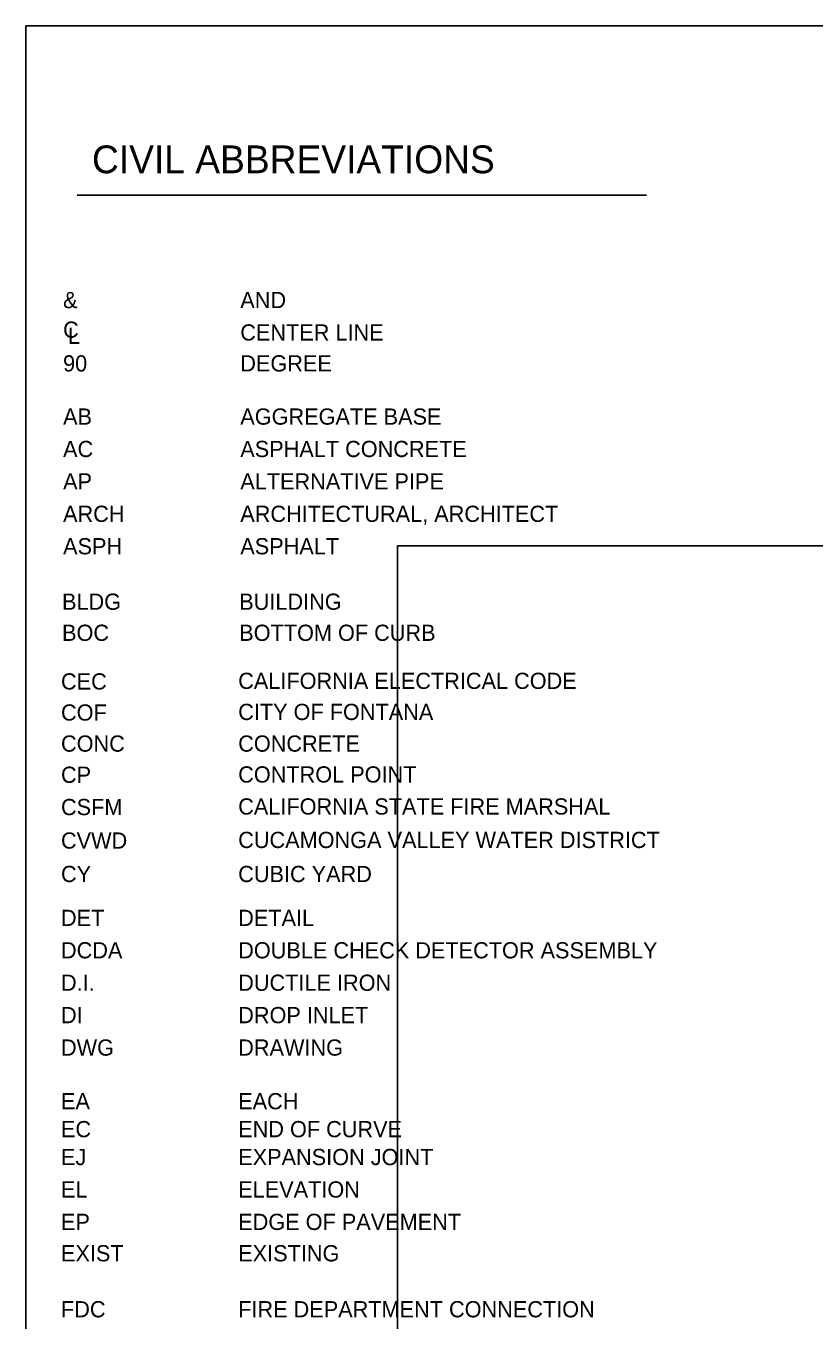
# Model space of a CAD drawing. Extents: x 6711682 to 6713077, y 1869209 to 1870525.
# Drawn here: x 6711682 to 6712022, y 1869939 to 1870497 of the extents above; entities that cross this region are included whole.
import ezdxf

# ---------------------------------------------------------------- set-up
doc = ezdxf.new("R2010")
doc.units = 0
for name, color, linetype in [('G-TTLB-VIEW', 7, 'Continuous'), ('Nongeo Data(60)', 7, 'Continuous'), ('Sheet Format(10)', 7, 'Continuous')]:
    doc.layers.add(name, color=color, linetype=linetype)

msp = doc.modelspace()

# ---------------------------------------------------------------- linework, layer by layer
at = {"layer": 'G-TTLB-VIEW'}
for points in [[(6711681.56, 1870497.47), (6713076.58, 1870497.47), (6713076.58, 1869377.45), (6711681.56, 1869377.45)], [(6711841.98, 1870272.86), (6712888.25, 1870272.86), (6712888.25, 1869432.85), (6711841.98, 1869432.85)]]:
    msp.add_lwpolyline(points, close=True, dxfattribs=at)
at = {"layer": 'Nongeo Data(60)'}
msp.add_line((6711703.77, 1870424.32), (6711949.47, 1870424.32), dxfattribs=at)

# ---------------------------------------------------------------- texts
msp.add_text('CIVIL ABBREVIATIONS', height=12, rotation=0, dxfattribs=at).set_placement((6711710.11, 1870433.83))
at = {"layer": 'Sheet Format(10)'}
for s, p in [('&', (6711697.62, 1870375.58)), ('AND', (6711774.13, 1870375.58)), ('C', (6711697.62, 1870362.79)), ('CENTER LINE', (6711774.13, 1870361.58)), ('L', (6711699.69, 1870360.11)), ('90', (6711697.62, 1870348.23)), ('DEGREE', (6711774.13, 1870348.23)), ('AB', (6711697.62, 1870325.26)), ('AGGREGATE BASE', (6711774.13, 1870325.26)), ('AC', (6711697.62, 1870311.26)), ('ASPHALT CONCRETE', (6711774.13, 1870311.26)), ('AP', (6711697.62, 1870297.26)), ('ALTERNATIVE PIPE', (6711774.13, 1870297.26)), ('ARCH', (6711697.62, 1870283.26)), ('ARCHITECTURAL, ARCHITECT', (6711774.13, 1870283.26)), ('ASPH', (6711697.62, 1870269.26)), ('ASPHALT', (6711774.13, 1870269.26)), ('BLDG', (6711697.17, 1870245.31)), ('BUILDING', (6711773.68, 1870245.31)), ('BOC', (6711697.17, 1870231.89)), ('BOTTOM OF CURB', (6711773.68, 1870231.89)), ('CEC', (6711696.72, 1870210.88)), ('CALIFORNIA ELECTRICAL CODE', (6711773.23, 1870211.13)), ('COF', (6711696.72, 1870197.46)), ('CITY OF FONTANA', (6711773.23, 1870197.71)), ('CONC', (6711696.72, 1870184.04)), ('CONCRETE', (6711773.23, 1870184.04)), ('CP', (6711696.72, 1870170.58)), ('CONTROL POINT', (6711773.23, 1870170.71)), ('CSFM', (6711696.72, 1870156.63)), ('CALIFORNIA STATE FIRE MARSHAL', (6711773.23, 1870156.88)), ('CUCAMONGA VALLEY WATER DISTRICT', (6711773.23, 1870142.43)), ('CVWD', (6711696.72, 1870142.17)), ('CY', (6711696.72, 1870127.72)), ('CUBIC YARD', (6711773.23, 1870127.72)), ('DET', (6711696.72, 1870108.77)), ('DETAIL', (6711773.23, 1870108.77)), ('DCDA', (6711696.72, 1870094.77)), ('DOUBLE CHECK DETECTOR ASSEMBLY', (6711773.23, 1870094.77)), ('D.I.', (6711696.72, 1870080.77)), ('DUCTILE IRON', (6711773.23, 1870080.77)), ('DI', (6711696.72, 1870066.77)), ('DROP INLET', (6711773.23, 1870066.77)), ('DWG', (6711696.72, 1870052.77)), ('DRAWING', (6711773.23, 1870052.77)), ('EA', (6711696.72, 1870029.61)), ('EACH', (6711773.23, 1870029.61)), ('EC', (6711696.72, 1870017.54)), ('END OF CURVE', (6711773.23, 1870017.54)), ('EJ', (6711696.72, 1870005.49)), ('EXPANSION JOINT', (6711773.23, 1870005.49)), ('EL', (6711696.72, 1869991.49)), ('ELEVATION', (6711773.23, 1869991.49)), ('EP', (6711696.72, 1869977.49)), ('EDGE OF PAVEMENT', (6711773.23, 1869977.49)), ('EXIST', (6711696.72, 1869963.93)), ('EXISTING', (6711773.23, 1869963.93)), ('FDC', (6711696.72, 1869939.76)), ('FIRE DEPARTMENT CONNECTION', (6711773.23, 1869939.76))]:
    msp.add_text(s, height=7, dxfattribs=at).set_placement(p)

doc.saveas('drawing.dxf')
